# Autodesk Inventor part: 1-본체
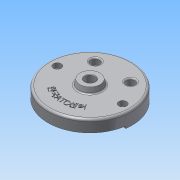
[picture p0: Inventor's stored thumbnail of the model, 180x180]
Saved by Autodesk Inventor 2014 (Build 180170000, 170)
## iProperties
Created: 2015-06
Part Number: 1-본체
Material: 알루미늄 6061
Document SubType Name: Modeling
Designer: Administrator
Density: 2.71 g/cm^3
Appearance: 알루미늄 - 평지
Mass: 1070.98 g
Surface Area: 1034.41 cm^2
Volume: 395.194 cm^3
Author: Administrator
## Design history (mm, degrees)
sketch "스케치1"
  geometry: C1 r 95 at (0, 0); 1 further point
  constraints: 1 centre point, 1 coincident
  dimensions: "d0" = 190 diameter of C1
extrude "돌출1" new body sketch "스케치1" distance "d1" = 32; taper "d2" = 0 deg
feature "쉘1" dims "d3" = 7, "d4" = 5
sketch "스케치2"
  geometry: C1 r 90 at (0, 0) reference; C2 r 15 at (-40, 52); C3 r 15 at (40, 52)
  constraints: 2 centre point, 1 equal radius
  dimensions: "d5" = 30 diameter of C2; "d6" = 40 horizontal distance of C1.centre C2.centre; "d7" = 40 horizontal distance of C1.centre C3.centre; "d8" = 52 vertical distance of C1.centre C2.centre; "d9" = 52 vertical distance of C1.centre C3.centre
extrude "돌출2" join sketch "스케치2" stored distance "d10" = 32; taper "d11" = 0 deg
sketch "스케치3"
  geometry: L1 (-6, -13.748)-(-6, 13.748); L2 (6, -13.748)-(6, 13.748); L3 (66.252, 6)-(93.748, 6); L4 (66.252, -6)-(93.748, -6); A1 r 15 centre (0, 0) between (-6, -13.748) and (-6, 13.748) reference; A2 r 15 centre (80, 0) between (66.252, 6) and (93.748, 6) reference; 1 further point
  constraints: 8 end point, 8 point on circle, 4 parallel, 1 perpendicular, 1 vertical
  dimensions: "d12" = 6 distance from line of A1.centre L1; "d13" = 12 distance between parallel lines of L4 L3
extrude "돌출3" cut sketch "스케치3" distance "d14" = 3; taper "d15" = 0 deg
sketch "스케치4"
  geometry: A1 r 15 centre (0, 0) between (-6, 13.748) and (-6, -13.748) reference; A2 r 15 centre (80, 0) between (93.748, 6) and (66.252, 6) reference; 3 further points
  constraints: 2 coincident
hole "구멍1" sketch "스케치4" at (0, 0), (80, 0) diameter "d16" = 20; stored, may be unused: countersink angle "d20" = 90 deg, drill point angle "d22" = 118 deg; dims "d17" = 6, "d18" = 4, "d19" = 2, "d21" = 8
sketch "스케치5"
  geometry: L1 (45.033, 16)-(75.657, 16); L2 (-75.657, 16)-(-45.033, 16); A1 r 90 centre (0, 0) between (-88.566, 16) and (88.566, 16) reference; A2 r 90 centre (0, 0) between (85.114, 29.25) and (-85.114, 29.25); A3 r 10 centre (-75.657, 26) between (-85.114, 29.25) and (-75.657, 16); A4 r 10 centre (75.657, 26) between (75.657, 16) and (85.114, 29.25); A5 r 42 centre (0, 0) between (36.373, 21) and (-36.373, 21); A6 r 10 centre (-45.033, 26) between (-45.033, 16) and (-36.373, 21); A7 r 10 centre (45.033, 26) between (36.373, 21) and (45.033, 16); 2 further points
  constraints: 18 point on circle, 10 tangent, 6 centre point, 6 point on line, 5 end point, 2 coincident, 1 collinear, 1 equal radius, 1 horizontal
  dimensions: "d23" = 16 distance from line of L1 A1.centre; "d24" = 10 radius of A3; "d25" = 84 diameter of A5; "d26" = 10 radius of A6; "d27" = 10 radius of A7
extrude "돌출4" join sketch "스케치5" distance "d28" = 7; taper "d29" = 0 deg
sketch "스케치6"
  geometry: C1 r 35 at (0, 0); A1 r 90 centre (0, 0) between (-85.114, 29.25) and (85.114, 29.25) reference
  constraints: 1 centre point, 1 coincident
  dimensions: "d30" = 70 diameter of C1
extrude "돌출5" join sketch "스케치6" distance "d31" = 10; taper "d32" = -10 deg
sketch "스케치7"
  geometry: L1 (0, 0)-(-94.075, -13.221); L2 (0, 0)-(94.075, -13.221); L3 (-95, 0)-(-90, 0); L4 (-35, 0)-(0, 0); L5 (0, 0)-(35, 0); L6 (90, 0)-(95, 0); A1 r 90 centre (0, 0) between (-90, 0) and (90, 0) reference; A2 r 95 centre (0, 0) between (-95, 0) and (-94.075, -13.221) reference; A3 r 35 centre (0, 0) between (-35, 0) and (35, 0) reference; A4 r 95 centre (0, 0) between (-94.075, -13.221) and (94.075, -13.221)
  constraints: 12 end point, 10 point on circle, 6 collinear, 2 horizontal, 1 centre point, 1 coincident
  dimensions: "d35" = 8 deg angle of L1 L3; "d36" = 8 deg angle of L2 L6
extrude "돌출6" cut sketch "스케치7" distance "d37" = 5; taper "d38" = 0 deg
sketch "스케치8"
  geometry: L1 (-45.033, 16)-(-75.657, 16) reference; L2 (-87.972, -19)-(87.972, -19); L3 (0, 0)-(0, -19); L4 (-87.972, -14)-(87.972, -14); L5 (-59, -19)-(-59, -14); L6 (-41, -19)-(-41, -14); L7 (41, -19)-(41, -14); L8 (59, -19)-(59, -14); C1 r 35 at (0, 0) reference; A1 r 90 centre (0, 0) between (-85.114, 29.25) and (85.114, 29.25) reference; A2 r 41 centre (0, -19) between (-41, -19) and (41, -19); A3 r 59 centre (0, -19) between (-59, -19) and (59, -19); A4 r 9 centre (-50, -14) between (-41, -14) and (-59, -14); A5 r 9 centre (50, -14) between (59, -14) and (41, -14)
  constraints: 14 end point, 10 point on circle, 8 point on line, 8 tangent, 4 centre point, 3 parallel, 3 perpendicular, 2 coincident, 1 midpoint
  dimensions: "d39" = 19 distance from line of L2 C1.centre; "d40" = 41 radius of A2; "d41" = 59 radius of A3; "d42" = 5 distance between parallel lines of L2 L4
extrude "돌출7" cut sketch "스케치8" distance "d43" = 7; taper "d44" = 0 deg
sketch "스케치9"
  geometry: C1 r 35 at (0, 0) reference; C2 r 9 at (-74, 0); C3 r 9 at (74, 0); A1 r 42 centre (0, 0) between (36.373, 21) and (-36.373, 21) reference; A2 r 15 centre (-40, 52) between (-34, 65.748) and (-46, 65.748) reference; A3 r 15 centre (40, 52) between (26.252, 58) and (26.252, 46) reference
  constraints: 2 centre point, 2 horizontal alignment, 1 equal radius
  dimensions: "d45" = 18 diameter of C2; "d47" = 74 distance of C1.centre C2.centre; "d48" = 74 distance of C3.centre A1.centre
extrude "돌출8" join sketch "스케치9" stored distance "d49" = 7; taper "d50" = 0 deg
sketch "스케치10"
  geometry: C1 r 9 at (-74, 0) reference; C2 r 9 at (74, 0) reference; 2 further points
  constraints: 2 coincident
hole "구멍2" sketch "스케치10" at (-74, 0), (74, 0) diameter "d51" = 11; stored, may be unused: countersink angle "d55" = 90 deg, drill point angle "d57" = 118 deg; dims "d52" = 6, "d53" = 18, "d54" = 11, "d56" = 8
sketch "스케치11"
  geometry: C1 r 95 at (0, 0) reference; C2 r 26 at (0, 0)
  constraints: 1 centre point, 1 coincident
  dimensions: "d69" = 52 diameter of C2
extrude "돌출9" join sketch "스케치11" distance "d70" = 12; taper "d71" = -15 deg
sketch "스케치12"
  geometry: C1 r 95 at (0, 0) reference; C2 r 68 at (0, 0)
  constraints: 1 centre point, 1 coincident, 1 other
  dimensions: "d72" = 136 diameter of C2
feature "엠보싱1" sketch "스케치12" dims "d73" = 0.5, "d74" = 0
fillet "모깎기1" dims "d75" = 3
fillet "모깎기2" dims "d76" = 3
fillet "모깎기3" dims "d77" = 5
fillet "모깎기4" dims "d78" = 1
fillet "모깎기5" dims "d79" = 3
fillet "모깎기6" dims "d80" = 3
chamfer "모따기1" distance "d81" = 1; stored, may be unused: second distance "d82" = 2, angle "d83" = 45 deg
fillet "모깎기7" dims "d84" = 3
hole "구멍5" diameter "d97" = 23; stored, may be unused: countersink angle "d101" = 90 deg, drill point angle "d103" = 118 deg; dims "d95" = 10, "d96" = 10, "d98" = 6, "d99" = 50, "d100" = 15, "d102" = 8
chamfer "모따기2" distance "d104" = 1; stored, may be unused: second distance "d105" = 2, angle "d106" = 45 deg
fillet "모깎기9" dims "d107" = 0.3
node "솔리드1"
other parameters: "d33" = 5 deg, "d34" = 5 deg
